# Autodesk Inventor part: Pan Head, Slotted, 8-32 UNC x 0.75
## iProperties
Author: Administrator
Shininess: 25.0
PropertySet Name: _Private Model Information
Created: 2001-03
Part Number: Pan Head, Slotted, 8-32 UNC x 0.75
Description: Pan Head, Slotted, 8-32 UNC x 0.75
Document SubType Name: Modeling
Designer: Administrator
Material: Steel, Mild
Control State: 0
Master: False
Checked Out: False
PropertySet Name: Design Tracking Control
Density: 7.860000000000001
Volumn: 0.3623567375054352
Area: 4.180399598208605
PropertySet Name: Model Information
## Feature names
1. Revolution1
2. Extrusion1
3. Chamfer1
